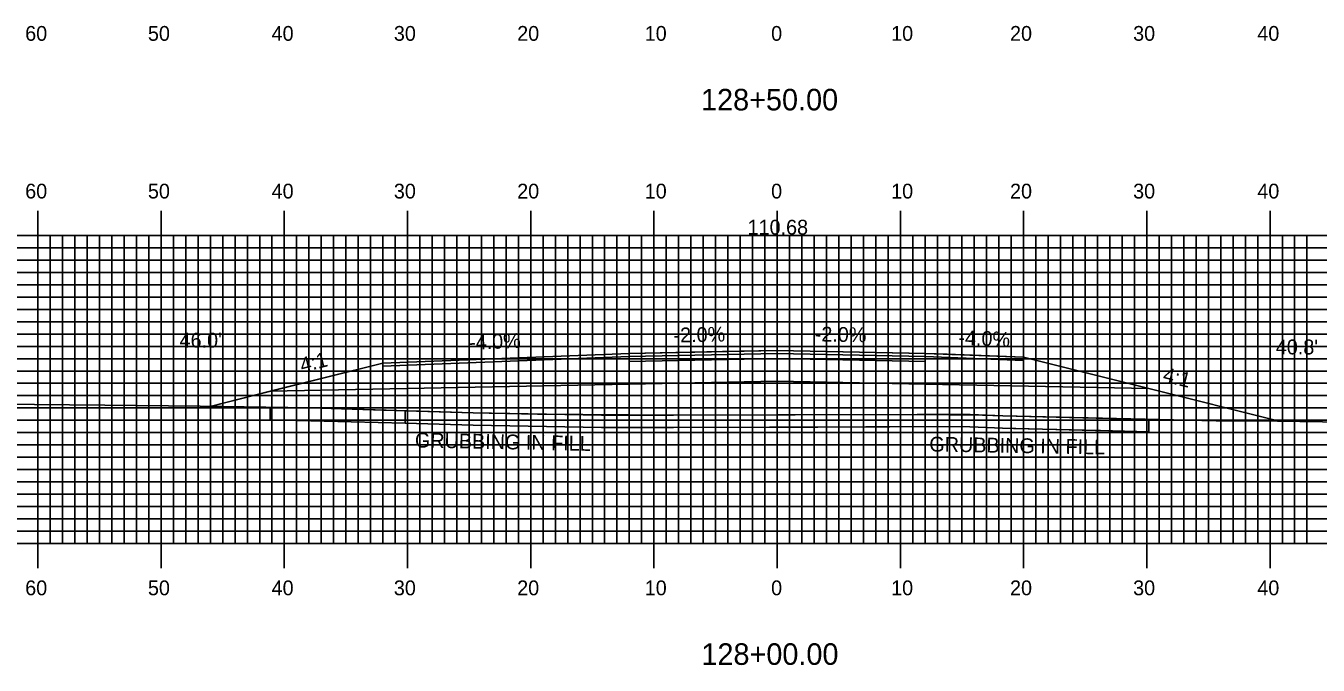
# Model space of a CAD drawing. Extents: x 1773596 to 1773940, y 442591 to 442811.
# Drawn here: x 1773701.2 to 1773806.1, y 442643.8 to 442695.7 of the extents above; entities that cross this region are included whole.
import ezdxf

# ---------------------------------------------------------------- set-up
doc = ezdxf.new("R2010")
doc.units = 0
for name, color, linetype in [('ANNOTATION', 7, 'Continuous'), ('D_Roadway_Centerline', 7, 'Continuous'), ('D_Roadway_Centerline_Text', 7, 'Continuous'), ('D_Roadway_Edge_Shoulder', 7, 'Continuous'), ('D_Roadway_Edge_TW', 7, 'Continuous'), ('D_Roadway_Pavement', 7, 'Continuous'), ('D_Roadway_SlopeLines', 7, 'Continuous'), ('D_Roadway_SubGrade', 7, 'Continuous'), ('D_Text_Standard', 7, 'Continuous'), ('GRUBBING IN FILL', 7, 'Continuous'), ('H_V ANNOTATION', 7, 'Continuous'), ('MAJOR', 7, 'Continuous'), ('MINOR', 7, 'Continuous'), ('S_Roadway_Centerline', 7, 'Continuous')]:
    doc.layers.add(name, color=color, linetype=linetype)

msp = doc.modelspace()

# ---------------------------------------------------------------- linework, layer by layer
at = {"layer": 'D_Roadway_Centerline'}
msp.add_lwpolyline([(1773716.12, 442664.8), (1773721.01, 442666.02), (1773730.15, 442668.3), (1773750.15, 442669.1), (1773757.71, 442669.26), (1773762.15, 442669.34), (1773772.87, 442669.13), (1773774.15, 442669.1), (1773775.94, 442669.03), (1773782.15, 442668.78), (1773784.86, 442668.11), (1773792.32, 442666.24), (1773802.9, 442663.6)], dxfattribs=at)
at = {"layer": 'D_Roadway_Edge_Shoulder'}
for points in [[(1773750.15, 442669.1), (1773730.15, 442668.3), (1773730.15, 442668.05), (1773750.15, 442668.85)], [(1773774.15, 442669.1), (1773782.15, 442668.78), (1773782.15, 442668.53), (1773774.15, 442668.85)]]:
    msp.add_lwpolyline(points, close=True, dxfattribs=at)
at = {"layer": 'D_Roadway_Edge_TW'}
msp.add_lwpolyline([(1773750.15, 442668.85), (1773750.15, 442669.1), (1773762.15, 442669.34), (1773774.15, 442669.1), (1773774.15, 442668.85), (1773762.15, 442669.09)], close=True, dxfattribs=at)
at = {"layer": 'D_Roadway_Pavement'}
msp.add_lwpolyline([(1773750.15, 442668.44), (1773750.15, 442668.85), (1773762.15, 442669.09), (1773774.15, 442668.85), (1773774.15, 442668.44), (1773762.15, 442668.68)], close=True, dxfattribs=at)
at = {"layer": 'D_Roadway_SlopeLines'}
for points in [[(1773782.15, 442668.78), (1773792.32, 442666.24), (1773802.9, 442663.6)], [(1773730.15, 442668.3), (1773719.97, 442665.76), (1773718.15, 442665.3), (1773716.12, 442664.8)]]:
    msp.add_lwpolyline(points, dxfattribs=at)
at = {"layer": 'D_Roadway_SubGrade'}
msp.add_lwpolyline([(1773750.15, 442666.6), (1773721.01, 442666.02), (1773730.15, 442668.3), (1773730.15, 442668.05), (1773750.15, 442668.85), (1773762.15, 442669.09), (1773774.15, 442668.85), (1773782.15, 442668.53), (1773782.15, 442668.78), (1773792.32, 442666.24), (1773774.15, 442666.6), (1773762.15, 442666.84)], close=True, dxfattribs=at)
at = {"layer": 'GRUBBING IN FILL'}
for p, q in [((1773724.23, 442664.67), (1773721.01, 442664.72)), ((1773724.23, 442664.67), (1773721.01, 442664.72)), ((1773731.97, 442664.44), (1773724.23, 442664.67)), ((1773731.97, 442664.44), (1773724.23, 442664.67)), ((1773731.97, 442664.44), (1773731.97, 442663.44)), ((1773731.97, 442664.44), (1773731.97, 442664.44)), ((1773731.97, 442663.44), (1773731.97, 442664.44)), ((1773731.97, 442663.44), (1773731.97, 442663.44)), ((1773792.32, 442663.74), (1773792.32, 442662.74)), ((1773792.32, 442663.74), (1773792.32, 442662.74))]:
    msp.add_line(p, q, dxfattribs=at)
for points in [[(1773721.01, 442664.72), (1773721.01, 442663.72), (1773731.97, 442663.44)], [(1773731.97, 442663.44), (1773721.01, 442663.72), (1773721.01, 442664.72)], [(1773721.01, 442664.72), (1773721.01, 442663.72), (1773731.97, 442663.44)], [(1773721.01, 442664.72), (1773721.01, 442663.72), (1773731.97, 442663.44)], [(1773731.97, 442664.44), (1773737.49, 442664.27), (1773742.69, 442664.18), (1773753.74, 442664.08), (1773762.15, 442664.11), (1773762.15, 442663.11), (1773753.74, 442663.08), (1773747.89, 442663.09), (1773737.47, 442663.27), (1773731.97, 442663.44)], [(1773731.97, 442663.44), (1773737.47, 442663.27), (1773747.89, 442663.09), (1773753.74, 442663.08), (1773777.15, 442663.17), (1773780.44, 442663.02), (1773792.32, 442662.74)], [(1773731.97, 442663.44), (1773737.47, 442663.27), (1773747.89, 442663.09), (1773753.74, 442663.08), (1773777.15, 442663.17), (1773780.44, 442663.02), (1773792.32, 442662.74)]]:
    msp.add_lwpolyline(points, dxfattribs=at)
for points in [[(1773731.97, 442664.44), (1773737.49, 442664.27), (1773742.69, 442664.18), (1773753.74, 442664.08), (1773762.15, 442664.11), (1773762.15, 442663.11), (1773753.74, 442663.08), (1773747.89, 442663.09), (1773737.47, 442663.27), (1773731.97, 442663.44)], [(1773762.15, 442664.11), (1773763.62, 442664.12), (1773773.51, 442664.15), (1773778.82, 442664.09), (1773780.47, 442664.02), (1773789.13, 442663.82), (1773792.32, 442663.74), (1773792.32, 442662.74), (1773788.38, 442662.84), (1773781.32, 442663), (1773780.44, 442663.02), (1773777.15, 442663.17), (1773765.44, 442663.12), (1773762.15, 442663.11)], [(1773762.15, 442664.11), (1773763.62, 442664.12), (1773773.51, 442664.15), (1773778.82, 442664.09), (1773780.47, 442664.02), (1773789.13, 442663.82), (1773792.32, 442663.74), (1773792.32, 442662.74), (1773788.38, 442662.84), (1773781.32, 442663), (1773780.44, 442663.02), (1773777.15, 442663.17), (1773765.44, 442663.12), (1773762.15, 442663.11)]]:
    msp.add_lwpolyline(points, close=True, dxfattribs=at)
at = {"layer": 'MAJOR'}
for p, q in [((1773702.15, 442680.67), (1773702.15, 442678.67)), ((1773712.15, 442680.67), (1773712.15, 442678.67)), ((1773722.15, 442680.67), (1773722.15, 442678.67)), ((1773732.15, 442680.67), (1773732.15, 442678.67)), ((1773742.15, 442680.67), (1773742.15, 442678.67)), ((1773752.15, 442680.67), (1773752.15, 442678.67)), ((1773762.15, 442680.67), (1773762.15, 442678.67)), ((1773772.15, 442680.67), (1773772.15, 442678.67)), ((1773782.15, 442680.67), (1773782.15, 442678.67)), ((1773792.15, 442680.67), (1773792.15, 442678.67)), ((1773802.15, 442680.67), (1773802.15, 442678.67)), ((1773622.15, 442678.67), (1773902.15, 442678.67)), ((1773622.15, 442678.67), (1773902.15, 442678.67)), ((1773702.15, 442653.67), (1773702.15, 442678.67)), ((1773712.15, 442653.67), (1773712.15, 442678.67)), ((1773722.15, 442653.67), (1773722.15, 442678.67)), ((1773732.15, 442653.67), (1773732.15, 442678.67)), ((1773742.15, 442653.67), (1773742.15, 442678.67)), ((1773752.15, 442653.67), (1773752.15, 442678.67)), ((1773762.15, 442653.67), (1773762.15, 442678.67)), ((1773772.15, 442653.67), (1773772.15, 442678.67)), ((1773782.15, 442653.67), (1773782.15, 442678.67)), ((1773792.15, 442653.67), (1773792.15, 442678.67)), ((1773802.15, 442653.67), (1773802.15, 442678.67)), ((1773622.15, 442673.67), (1773902.15, 442673.67)), ((1773622.15, 442668.67), (1773902.15, 442668.67)), ((1773622.15, 442663.67), (1773902.15, 442663.67)), ((1773622.15, 442658.67), (1773902.15, 442658.67)), ((1773622.15, 442653.67), (1773902.15, 442653.67)), ((1773622.15, 442653.67), (1773902.15, 442653.67)), ((1773702.15, 442651.66), (1773702.15, 442653.67)), ((1773712.15, 442651.66), (1773712.15, 442653.67)), ((1773722.15, 442651.66), (1773722.15, 442653.67)), ((1773732.15, 442651.66), (1773732.15, 442653.67)), ((1773742.15, 442651.66), (1773742.15, 442653.67)), ((1773752.15, 442651.66), (1773752.15, 442653.67)), ((1773762.15, 442651.66), (1773762.15, 442653.67)), ((1773772.15, 442651.66), (1773772.15, 442653.67)), ((1773782.15, 442651.66), (1773782.15, 442653.67)), ((1773792.15, 442651.66), (1773792.15, 442653.67)), ((1773802.15, 442651.66), (1773802.15, 442653.67))]:
    msp.add_line(p, q, dxfattribs=at)
at = {"layer": 'MINOR'}
for p, q in [((1773703.15, 442653.67), (1773703.15, 442678.67)), ((1773704.15, 442653.67), (1773704.15, 442678.67)), ((1773705.15, 442653.67), (1773705.15, 442678.67)), ((1773706.15, 442653.67), (1773706.15, 442678.67)), ((1773707.15, 442653.67), (1773707.15, 442678.67)), ((1773708.15, 442653.67), (1773708.15, 442678.67)), ((1773709.15, 442653.67), (1773709.15, 442678.67)), ((1773710.15, 442653.67), (1773710.15, 442678.67)), ((1773711.15, 442653.67), (1773711.15, 442678.67)), ((1773713.15, 442653.67), (1773713.15, 442678.67)), ((1773714.15, 442653.67), (1773714.15, 442678.67)), ((1773715.15, 442653.67), (1773715.15, 442678.67)), ((1773716.15, 442653.67), (1773716.15, 442678.67)), ((1773717.15, 442653.67), (1773717.15, 442678.67)), ((1773718.15, 442653.67), (1773718.15, 442678.67)), ((1773719.15, 442653.67), (1773719.15, 442678.67)), ((1773720.15, 442653.67), (1773720.15, 442678.67)), ((1773721.15, 442653.67), (1773721.15, 442678.67)), ((1773723.15, 442653.67), (1773723.15, 442678.67)), ((1773724.15, 442653.67), (1773724.15, 442678.67)), ((1773725.15, 442653.67), (1773725.15, 442678.67)), ((1773726.15, 442653.67), (1773726.15, 442678.67)), ((1773727.15, 442653.67), (1773727.15, 442678.67)), ((1773728.15, 442653.67), (1773728.15, 442678.67)), ((1773729.15, 442653.67), (1773729.15, 442678.67)), ((1773730.15, 442653.67), (1773730.15, 442678.67)), ((1773731.15, 442653.67), (1773731.15, 442678.67)), ((1773733.15, 442653.67), (1773733.15, 442678.67)), ((1773734.15, 442653.67), (1773734.15, 442678.67)), ((1773735.15, 442653.67), (1773735.15, 442678.67)), ((1773736.15, 442653.67), (1773736.15, 442678.67)), ((1773737.15, 442653.67), (1773737.15, 442678.67)), ((1773738.15, 442653.67), (1773738.15, 442678.67)), ((1773739.15, 442653.67), (1773739.15, 442678.67)), ((1773740.15, 442653.67), (1773740.15, 442678.67)), ((1773741.15, 442653.67), (1773741.15, 442678.67)), ((1773743.15, 442653.67), (1773743.15, 442678.67)), ((1773744.15, 442653.67), (1773744.15, 442678.67)), ((1773745.15, 442653.67), (1773745.15, 442678.67)), ((1773746.15, 442653.67), (1773746.15, 442678.67)), ((1773747.15, 442653.67), (1773747.15, 442678.67)), ((1773748.15, 442653.67), (1773748.15, 442678.67)), ((1773749.15, 442653.67), (1773749.15, 442678.67)), ((1773750.15, 442653.67), (1773750.15, 442678.67)), ((1773751.15, 442653.67), (1773751.15, 442678.67)), ((1773753.15, 442653.67), (1773753.15, 442678.67)), ((1773754.15, 442653.67), (1773754.15, 442678.67)), ((1773755.15, 442653.67), (1773755.15, 442678.67)), ((1773756.15, 442653.67), (1773756.15, 442678.67)), ((1773757.15, 442653.67), (1773757.15, 442678.67)), ((1773758.15, 442653.67), (1773758.15, 442678.67)), ((1773759.15, 442653.67), (1773759.15, 442678.67)), ((1773760.15, 442653.67), (1773760.15, 442678.67)), ((1773761.15, 442653.67), (1773761.15, 442678.67)), ((1773763.15, 442653.67), (1773763.15, 442678.67)), ((1773764.15, 442653.67), (1773764.15, 442678.67)), ((1773765.15, 442653.67), (1773765.15, 442678.67)), ((1773766.15, 442653.67), (1773766.15, 442678.67)), ((1773767.15, 442653.67), (1773767.15, 442678.67)), ((1773768.15, 442653.67), (1773768.15, 442678.67)), ((1773769.15, 442653.67), (1773769.15, 442678.67)), ((1773770.15, 442653.67), (1773770.15, 442678.67)), ((1773771.15, 442653.67), (1773771.15, 442678.67)), ((1773773.15, 442653.67), (1773773.15, 442678.67)), ((1773774.15, 442653.67), (1773774.15, 442678.67)), ((1773775.15, 442653.67), (1773775.15, 442678.67)), ((1773776.15, 442653.67), (1773776.15, 442678.67)), ((1773777.15, 442653.67), (1773777.15, 442678.67)), ((1773778.15, 442653.67), (1773778.15, 442678.67)), ((1773779.15, 442653.67), (1773779.15, 442678.67)), ((1773780.15, 442653.67), (1773780.15, 442678.67)), ((1773781.15, 442653.67), (1773781.15, 442678.67)), ((1773783.15, 442653.67), (1773783.15, 442678.67)), ((1773784.15, 442653.67), (1773784.15, 442678.67)), ((1773785.15, 442653.67), (1773785.15, 442678.67)), ((1773786.15, 442653.67), (1773786.15, 442678.67)), ((1773787.15, 442653.67), (1773787.15, 442678.67)), ((1773788.15, 442653.67), (1773788.15, 442678.67)), ((1773789.15, 442653.67), (1773789.15, 442678.67)), ((1773790.15, 442653.67), (1773790.15, 442678.67)), ((1773791.15, 442653.67), (1773791.15, 442678.67)), ((1773793.15, 442653.67), (1773793.15, 442678.67)), ((1773794.15, 442653.67), (1773794.15, 442678.67)), ((1773795.15, 442653.67), (1773795.15, 442678.67)), ((1773796.15, 442653.67), (1773796.15, 442678.67)), ((1773797.15, 442653.67), (1773797.15, 442678.67)), ((1773798.15, 442653.67), (1773798.15, 442678.67)), ((1773799.15, 442653.67), (1773799.15, 442678.67)), ((1773800.15, 442653.67), (1773800.15, 442678.67)), ((1773801.15, 442653.67), (1773801.15, 442678.67)), ((1773803.15, 442653.67), (1773803.15, 442678.67)), ((1773804.15, 442653.67), (1773804.15, 442678.67)), ((1773805.15, 442653.67), (1773805.15, 442678.67)), ((1773622.15, 442677.67), (1773902.15, 442677.67)), ((1773622.15, 442676.67), (1773902.15, 442676.67)), ((1773622.15, 442675.67), (1773902.15, 442675.67)), ((1773622.15, 442674.67), (1773902.15, 442674.67)), ((1773622.15, 442672.67), (1773902.15, 442672.67)), ((1773622.15, 442671.67), (1773902.15, 442671.67)), ((1773622.15, 442670.67), (1773902.15, 442670.67)), ((1773622.15, 442669.67), (1773902.15, 442669.67)), ((1773622.15, 442667.67), (1773902.15, 442667.67)), ((1773622.15, 442666.67), (1773902.15, 442666.67)), ((1773622.15, 442665.67), (1773902.15, 442665.67)), ((1773622.15, 442664.67), (1773902.15, 442664.67)), ((1773622.15, 442662.67), (1773902.15, 442662.67)), ((1773622.15, 442661.67), (1773902.15, 442661.67)), ((1773622.15, 442660.67), (1773902.15, 442660.67)), ((1773622.15, 442659.67), (1773902.15, 442659.67)), ((1773622.15, 442657.67), (1773902.15, 442657.67)), ((1773622.15, 442656.67), (1773902.15, 442656.67)), ((1773622.15, 442655.67), (1773902.15, 442655.67)), ((1773622.15, 442654.67), (1773902.15, 442654.67))]:
    msp.add_line(p, q, dxfattribs=at)
at = {"layer": 'S_Roadway_Centerline'}
msp.add_lwpolyline([(1773698.97, 442664.99), (1773707.58, 442664.91), (1773715.33, 442664.81), (1773724.23, 442664.67), (1773737.49, 442664.27), (1773747.9, 442664.09), (1773753.74, 442664.08), (1773773.51, 442664.15), (1773777.17, 442664.17), (1773780.47, 442664.02), (1773797.79, 442663.62), (1773802.76, 442663.6), (1773811.88, 442663.47)], dxfattribs=at)

# ---------------------------------------------------------------- texts
at = {"layer": 'ANNOTATION'}
for s, rotation, p in [('-4.0%', 2.2906, (1773737.17, 442669.39)), ('-2.0%', 1.1458, (1773753.75, 442669.98)), ('-2.0%', 358.8543, (1773765.19, 442670.08)), ('-4.0%', 357.7094, (1773776.84, 442669.8)), ('4:1', 14.0389, (1773723.59, 442667.53)), ('4:1', 345.9635, (1773793.38, 442666.84))]:
    msp.add_text(s, height=1.2, rotation=rotation, dxfattribs=at).set_placement(p)
at = {"layer": 'D_Roadway_Centerline'}
for s, p in [('C', (1773762.14, 442669.34)), ('L', (1773762.15, 442669.34))]:
    msp.add_text(s, height=0.0146, dxfattribs=at).set_placement(p)
at = {"layer": 'D_Roadway_Centerline_Text'}
msp.add_text('110.68', height=1.2, dxfattribs=at).set_placement((1773759.75, 442678.74))
at = {"layer": 'D_Text_Standard'}
for s, p in [("46.0'", (1773713.65, 442669.57)), ("40.8'", (1773802.62, 442669.02))]:
    msp.add_text(s, height=1.2, dxfattribs=at).set_placement(p)
at = {"layer": 'GRUBBING IN FILL'}
for rotation, p in [(358.8448, (1773732.74, 442661.47)), (359.0192, (1773774.49, 442661.14))]:
    msp.add_text('GRUBBING IN FILL', height=1.2, rotation=rotation, dxfattribs=at).set_placement(p)
at = {"layer": 'H_V ANNOTATION'}
for s, height, p in [('60', 1.2, (1773701.12, 442694.47)), ('50', 1.2, (1773711.08, 442694.47)), ('40', 1.2, (1773721.12, 442694.47)), ('30', 1.2, (1773731.04, 442694.47)), ('20', 1.2, (1773741.05, 442694.47)), ('10', 1.2, (1773751.4, 442694.47)), ('0', 1.2, (1773761.66, 442694.47)), ('10', 1.2, (1773771.4, 442694.47)), ('20', 1.2, (1773781.05, 442694.47)), ('30', 1.2, (1773791.04, 442694.47)), ('40', 1.2, (1773801.12, 442694.47)), ('128+50.00', 1.75, (1773755.97, 442688.82)), ('60', 1.2, (1773701.12, 442681.67)), ('50', 1.2, (1773711.08, 442681.67)), ('40', 1.2, (1773721.12, 442681.67)), ('30', 1.2, (1773731.04, 442681.67)), ('20', 1.2, (1773741.05, 442681.67)), ('10', 1.2, (1773751.4, 442681.67)), ('0', 1.2, (1773761.66, 442681.67)), ('10', 1.2, (1773771.4, 442681.67)), ('20', 1.2, (1773781.05, 442681.67)), ('30', 1.2, (1773791.04, 442681.67)), ('40', 1.2, (1773801.12, 442681.67)), ('60', 1.2, (1773701.12, 442649.47)), ('50', 1.2, (1773711.08, 442649.47)), ('40', 1.2, (1773721.12, 442649.47)), ('30', 1.2, (1773731.04, 442649.47)), ('20', 1.2, (1773741.05, 442649.47)), ('10', 1.2, (1773751.4, 442649.47)), ('0', 1.2, (1773761.66, 442649.47)), ('10', 1.2, (1773771.4, 442649.47)), ('20', 1.2, (1773781.05, 442649.47)), ('30', 1.2, (1773791.04, 442649.47)), ('40', 1.2, (1773801.12, 442649.47)), ('128+00.00', 1.75, (1773756, 442643.82))]:
    msp.add_text(s, height=height, dxfattribs=at).set_placement(p)

doc.saveas('drawing.dxf')
